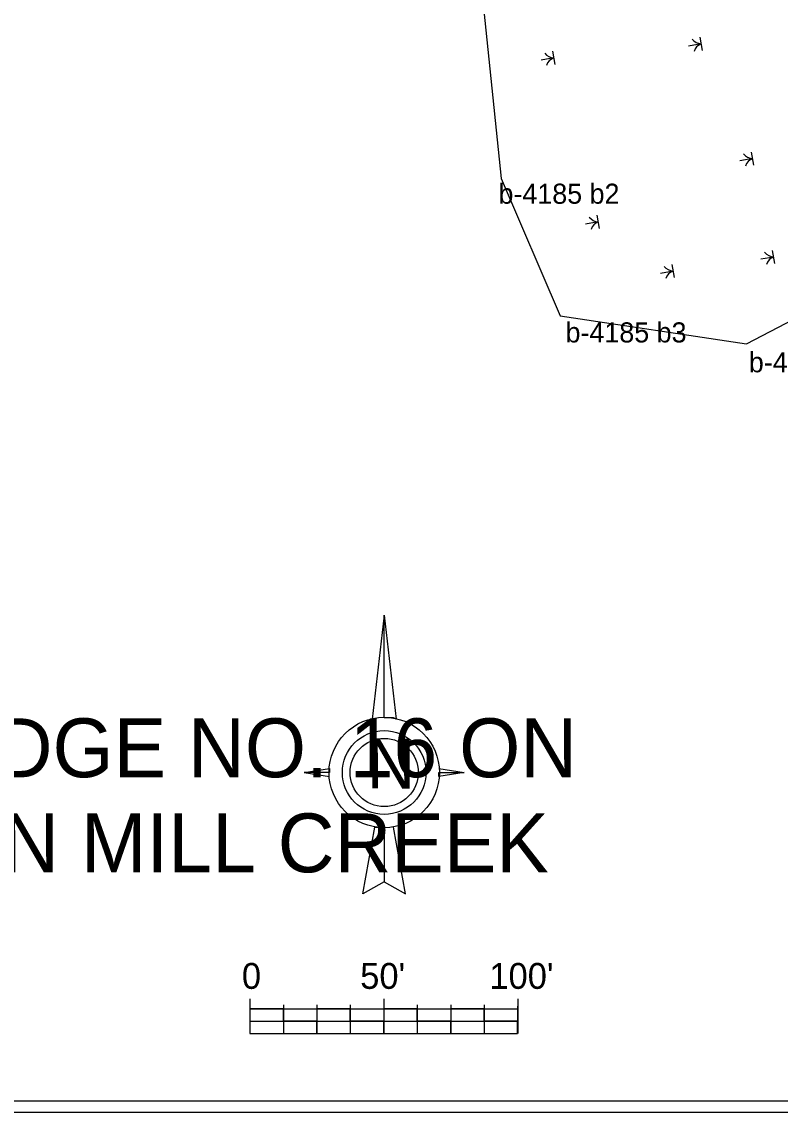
# Model space of a CAD drawing. Extents: x 2598976 to 2600165, y 728604 to 730243.
# Drawn here: x 2599361.3 to 2599644.5, y 728645.5 to 729052.5 of the extents above; entities that cross this region are included whole.
import ezdxf

# ---------------------------------------------------------------- set-up
doc = ezdxf.new("R2010")
doc.units = 0
for name, color, linetype in [('Old_Level_24', 7, 'Continuous'), ('Old_Level_3', 7, 'Continuous'), ('Old_Level_57', 7, 'Continuous'), ('Old_Level_63', 7, 'Continuous')]:
    doc.layers.add(name, color=color, linetype=linetype)

msp = doc.modelspace()

# ---------------------------------------------------------------- linework, layer by layer
at = {"layer": 'Old_Level_3'}
for p, q in [((2599540.31, 728994.01), (2599540.31, 728994.01)), ((2599562.39, 728942.84), (2599562.39, 728942.84)), ((2599631.97, 728932.34), (2599631.97, 728932.34))]:
    msp.add_line(p, q, dxfattribs=at)
at = {"layer": 'Old_Level_57'}
for p, q in [((2599615.07, 729044.32), (2599610.28, 729043.46)), ((2599615.5, 729041.85), (2599614.63, 729046.78)), ((2599560.45, 729036.61), (2599559.57, 729041.53)), ((2599560.01, 729039.07), (2599555.22, 729038.22)), ((2599634.73, 728999.01), (2599633.85, 729003.94)), ((2599634.29, 729001.47), (2599629.5, 729000.62)), ((2599577.05, 728975.41), (2599576.17, 728980.33)), ((2599576.61, 728977.87), (2599571.82, 728977.01)), ((2599642.6, 728962.29), (2599641.72, 728967.21)), ((2599642.16, 728964.75), (2599637.37, 728963.9)), ((2599604.58, 728959.51), (2599599.79, 728958.65)), ((2599605.02, 728957.05), (2599604.14, 728961.97))]:
    msp.add_line(p, q, dxfattribs=at)
msp.add_lwpolyline([(2599516.89, 729220.46), (2599540.31, 728994.01), (2599562.39, 728942.84), (2599631.97, 728932.34), (2599687.87, 728961.4), (2599745.82, 728966.7)], dxfattribs=at)
for centre, radius, start, end in [((2599615.53, 729049.45), 5.15, 220.9003, 264.248), ((2599616.11, 729040.56), 3.87, 105.6535, 165.9943), ((2599560.48, 729044.2), 5.15, 220.9003, 264.248), ((2599561.06, 729035.32), 3.87, 105.6535, 165.9943), ((2599634.76, 729006.61), 5.15, 220.9003, 264.248), ((2599635.34, 728997.72), 3.87, 105.6535, 165.9943), ((2599577.08, 728983), 5.15, 220.9003, 264.248), ((2599577.66, 728974.12), 3.87, 105.6535, 165.9943), ((2599642.63, 728969.89), 5.15, 220.9003, 264.248), ((2599643.21, 728961), 3.87, 105.6535, 165.9943), ((2599605.05, 728964.64), 5.15, 220.9003, 264.248), ((2599605.63, 728955.76), 3.87, 105.6535, 165.9943)]:
    msp.add_arc(centre, radius, start, end, dxfattribs=at)
at = {"layer": 'Old_Level_63'}
for p, q in [((2599496.69, 728831.08), (2599492.18, 728792.25)), ((2599466.79, 728772.36), (2599476.24, 728770.87)), ((2599517.06, 728773.82), (2599526.51, 728772.33)), ((2599496.63, 728751.94), (2599496.62, 728731.53)), ((2599504.57, 728727.04), (2599500.11, 728751.93)), ((2599496.12, 728731.03), (2599496.12, 728731.03)), ((2599496.62, 728731.53), (2599504.57, 728727.04)), ((2599497.12, 728731.03), (2599497.12, 728731.03)), ((2599446.5, 728687.8), (2599446.5, 728674.94)), ((2599446.5, 728687.8), (2599446.5, 728674.94)), ((2599446.5, 728687.8), (2599446.5, 728674.94)), ((2599459, 728685.62), (2599459, 728674.94)), ((2599459, 728685.62), (2599459, 728674.94)), ((2599459, 728685.62), (2599459, 728674.94)), ((2599471.5, 728685.62), (2599471.5, 728674.94)), ((2599471.5, 728685.62), (2599471.5, 728674.94)), ((2599471.5, 728685.62), (2599471.5, 728674.94)), ((2599484, 728685.62), (2599484, 728674.94)), ((2599484, 728685.62), (2599484, 728674.94)), ((2599484, 728685.62), (2599484, 728674.94)), ((2599496.5, 728687.8), (2599496.5, 728674.94)), ((2599496.5, 728687.8), (2599496.5, 728674.94)), ((2599496.5, 728687.8), (2599496.5, 728674.94)), ((2599509, 728685.62), (2599509, 728674.94)), ((2599509, 728685.62), (2599509, 728674.94)), ((2599509, 728685.62), (2599509, 728674.94)), ((2599521.5, 728685.62), (2599521.5, 728674.94)), ((2599521.5, 728685.62), (2599521.5, 728674.94)), ((2599521.5, 728685.62), (2599521.5, 728674.94)), ((2599534, 728685.62), (2599534, 728674.94)), ((2599534, 728685.62), (2599534, 728674.94)), ((2599534, 728685.62), (2599534, 728674.94)), ((2599546.5, 728687.8), (2599546.5, 728674.94)), ((2599546.5, 728687.8), (2599546.5, 728674.94)), ((2599546.5, 728687.8), (2599546.5, 728674.94)), ((2599446.5, 728684.15), (2599546.49, 728684.15)), ((2599459, 728684.15), (2599446.5, 728684.15)), ((2599446.5, 728684.15), (2599446.5, 728679.55)), ((2599446.5, 728684.15), (2599546.49, 728684.15)), ((2599459, 728684.15), (2599446.5, 728684.15)), ((2599446.5, 728684.15), (2599446.5, 728679.55)), ((2599446.5, 728684.15), (2599546.49, 728684.15)), ((2599459, 728684.15), (2599446.5, 728684.15)), ((2599446.5, 728684.15), (2599446.5, 728679.55)), ((2599459, 728679.55), (2599459, 728684.15)), ((2599459, 728679.55), (2599459, 728684.15)), ((2599459, 728679.55), (2599459, 728684.15)), ((2599484, 728684.15), (2599471.5, 728684.15)), ((2599471.5, 728684.15), (2599471.5, 728679.55)), ((2599484, 728684.15), (2599471.5, 728684.15)), ((2599471.5, 728684.15), (2599471.5, 728679.55)), ((2599484, 728684.15), (2599471.5, 728684.15)), ((2599471.5, 728684.15), (2599471.5, 728679.55)), ((2599484, 728679.55), (2599484, 728684.15)), ((2599484, 728679.55), (2599484, 728684.15)), ((2599484, 728679.55), (2599484, 728684.15)), ((2599509, 728684.15), (2599496.5, 728684.15)), ((2599496.5, 728684.15), (2599496.5, 728679.55)), ((2599509, 728684.15), (2599496.5, 728684.15)), ((2599496.5, 728684.15), (2599496.5, 728679.55)), ((2599509, 728684.15), (2599496.5, 728684.15)), ((2599496.5, 728684.15), (2599496.5, 728679.55)), ((2599509, 728679.55), (2599509, 728684.15)), ((2599509, 728679.55), (2599509, 728684.15)), ((2599509, 728679.55), (2599509, 728684.15)), ((2599534, 728684.15), (2599521.5, 728684.15)), ((2599521.5, 728684.15), (2599521.5, 728679.55)), ((2599534, 728684.15), (2599521.5, 728684.15)), ((2599521.5, 728684.15), (2599521.5, 728679.55)), ((2599534, 728684.15), (2599521.5, 728684.15)), ((2599521.5, 728684.15), (2599521.5, 728679.55)), ((2599534, 728679.55), (2599534, 728684.15)), ((2599534, 728679.55), (2599534, 728684.15)), ((2599534, 728679.55), (2599534, 728684.15)), ((2599546.49, 728685.17), (2599546.49, 728679.55)), ((2599546.49, 728685.17), (2599546.49, 728679.55)), ((2599546.49, 728685.17), (2599546.49, 728679.55)), ((2599446.5, 728679.55), (2599546.49, 728679.55)), ((2599446.5, 728679.55), (2599459, 728679.55)), ((2599446.5, 728679.55), (2599546.49, 728679.55)), ((2599446.5, 728679.55), (2599459, 728679.55)), ((2599446.5, 728679.55), (2599546.49, 728679.55)), ((2599446.5, 728679.55), (2599459, 728679.55)), ((2599471.5, 728679.55), (2599459, 728679.55)), ((2599459, 728679.55), (2599459, 728674.94)), ((2599471.5, 728679.55), (2599459, 728679.55)), ((2599459, 728679.55), (2599459, 728674.94)), ((2599471.5, 728679.55), (2599459, 728679.55)), ((2599459, 728679.55), (2599459, 728674.94)), ((2599471.5, 728674.94), (2599471.5, 728679.55)), ((2599471.5, 728679.55), (2599484, 728679.55)), ((2599471.5, 728674.94), (2599471.5, 728679.55)), ((2599471.5, 728679.55), (2599484, 728679.55)), ((2599471.5, 728674.94), (2599471.5, 728679.55)), ((2599471.5, 728679.55), (2599484, 728679.55)), ((2599496.5, 728679.55), (2599484, 728679.55)), ((2599484, 728679.55), (2599484, 728674.94)), ((2599496.5, 728679.55), (2599484, 728679.55)), ((2599484, 728679.55), (2599484, 728674.94)), ((2599496.5, 728679.55), (2599484, 728679.55)), ((2599484, 728679.55), (2599484, 728674.94)), ((2599496.5, 728674.94), (2599496.5, 728679.55)), ((2599496.5, 728679.55), (2599509, 728679.55)), ((2599496.5, 728674.94), (2599496.5, 728679.55)), ((2599496.5, 728679.55), (2599509, 728679.55)), ((2599496.5, 728674.94), (2599496.5, 728679.55)), ((2599496.5, 728679.55), (2599509, 728679.55)), ((2599521.5, 728679.55), (2599509, 728679.55)), ((2599509, 728679.55), (2599509, 728674.94)), ((2599521.5, 728679.55), (2599509, 728679.55)), ((2599509, 728679.55), (2599509, 728674.94)), ((2599521.5, 728679.55), (2599509, 728679.55)), ((2599509, 728679.55), (2599509, 728674.94)), ((2599521.5, 728674.94), (2599521.5, 728679.55)), ((2599521.5, 728679.55), (2599534, 728679.55)), ((2599521.5, 728674.94), (2599521.5, 728679.55)), ((2599521.5, 728679.55), (2599534, 728679.55)), ((2599521.5, 728674.94), (2599521.5, 728679.55)), ((2599521.5, 728679.55), (2599534, 728679.55)), ((2599546.49, 728679.55), (2599533.99, 728679.55)), ((2599533.99, 728679.55), (2599533.99, 728674.94)), ((2599546.49, 728679.55), (2599533.99, 728679.55)), ((2599533.99, 728679.55), (2599533.99, 728674.94)), ((2599546.49, 728679.55), (2599533.99, 728679.55)), ((2599533.99, 728679.55), (2599533.99, 728674.94)), ((2599546.49, 728674.94), (2599546.49, 728679.55)), ((2599546.49, 728674.94), (2599546.49, 728679.55)), ((2599546.49, 728674.94), (2599546.49, 728679.55)), ((2599446.5, 728674.94), (2599546.49, 728674.94)), ((2599446.5, 728674.94), (2599546.49, 728674.94)), ((2599446.5, 728674.94), (2599546.49, 728674.94)), ((2599459, 728674.94), (2599471.5, 728674.94)), ((2599459, 728674.94), (2599471.5, 728674.94)), ((2599459, 728674.94), (2599471.5, 728674.94)), ((2599484, 728674.94), (2599496.5, 728674.94)), ((2599484, 728674.94), (2599496.5, 728674.94)), ((2599484, 728674.94), (2599496.5, 728674.94)), ((2599509, 728674.94), (2599521.5, 728674.94)), ((2599509, 728674.94), (2599521.5, 728674.94)), ((2599509, 728674.94), (2599521.5, 728674.94)), ((2599533.99, 728674.94), (2599546.49, 728674.94)), ((2599533.99, 728674.94), (2599546.49, 728674.94)), ((2599533.99, 728674.94), (2599546.49, 728674.94)), ((2599010.83, 728649.84), (2599994.19, 728649.84)), ((2599010.83, 728649.84), (2599994.19, 728649.84)), ((2599010.83, 728649.84), (2599994.19, 728649.84)), ((2599010.83, 728645.54), (2599994.19, 728645.54)), ((2599010.83, 728645.54), (2599994.19, 728645.54)), ((2599010.83, 728645.54), (2599994.19, 728645.54))]:
    msp.add_line(p, q, dxfattribs=at)
for points in [[(2599496.69, 728831.08), (2599501.14, 728792.25), (2599500.15, 728792.75), (2599499.15, 728792.75), (2599498.16, 728792.75), (2599497.16, 728792.75), (2599496.66, 728792.76)], [(2599466.79, 728772.36), (2599476.25, 728773.86), (2599476.25, 728773.35), (2599476.25, 728773.35), (2599476.24, 728772.86), (2599476.24, 728772.36), (2599476.24, 728772.36)], [(2599517.06, 728772.33), (2599526.51, 728772.33), (2599517.05, 728770.84), (2599517.05, 728771.33), (2599517.05, 728771.83), (2599517.05, 728771.83)], [(2599493.15, 728751.94), (2599494.64, 728751.94), (2599495.14, 728751.93), (2599496.14, 728751.94), (2599496.63, 728751.94), (2599496.62, 728731.53), (2599488.65, 728727.06)]]:
    msp.add_lwpolyline(points, close=True, dxfattribs=at)
for major_axis in [(0, -20.61), (0, -15.63), (0, -12.74)]:
    msp.add_ellipse((2599496.65, 728772.34), major_axis=major_axis, ratio=0.999962, dxfattribs=at)

# ---------------------------------------------------------------- texts
at = {"layer": 'Old_Level_24'}
for s, p in [('b-4185 b2', (2599539.35, 728984.63)), ('b-4185 b3', (2599564.39, 728932.86)), ('b-4185 b4', (2599632.84, 728921.72))]:
    msp.add_text(s, height=7.5, dxfattribs=at).set_placement(p)
at = {"layer": 'Old_Level_63'}
for s, height, p in [('REPLACEMENT OF BRIDGE NO. 16 ON', 21.9724, (2599025.04, 728770.57)), ('NC 171 OVER HARDISON MILL CREEK', 21.9724, (2599020.92, 728735.08)), ('0', 9.65, (2599443.5, 728691.58)), ('0', 9.65, (2599443.5, 728691.58)), ('0', 9.65, (2599443.5, 728691.58)), ("50'", 9.645, (2599487.68, 728691.58)), ("100'", 9.645, (2599535.91, 728691.58))]:
    msp.add_text(s, height=height, dxfattribs=at).set_placement(p)
msp.add_text('N', height=18.67, rotation=359.9586, dxfattribs=at).set_placement((2599490.17, 728766.37))

doc.saveas('drawing.dxf')
